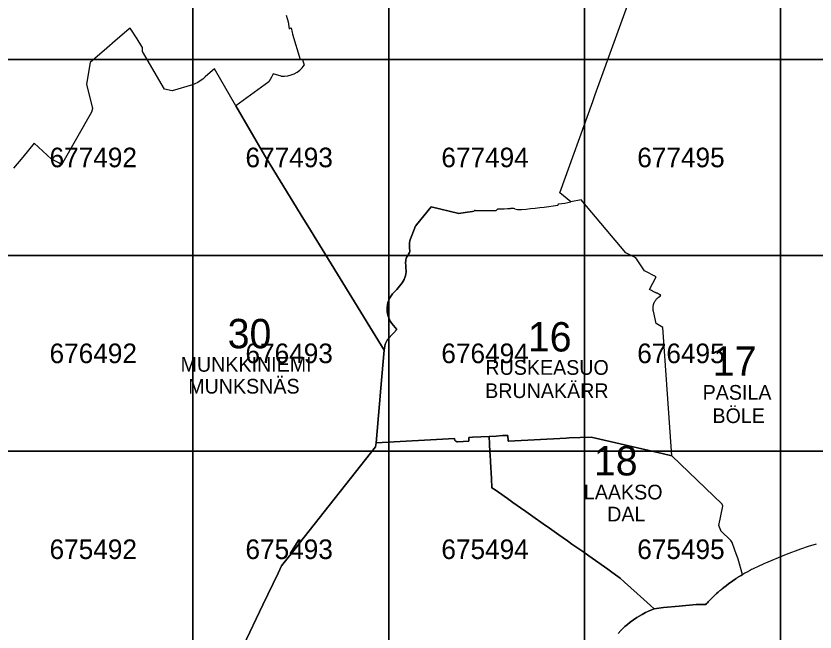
# Model space of a CAD drawing. Extents: x 25485000 to 25520000, y 6656775 to 6690000.
# Drawn here: x 25492097 to 25496176, y 6675077 to 6678222 of the extents above; entities that cross this region are included whole.
import ezdxf

# ---------------------------------------------------------------- set-up
doc = ezdxf.new("R2010")
doc.units = 0
doc.layers.add('Level 63', color=7, linetype='Continuous')

msp = doc.modelspace()

# ---------------------------------------------------------------- linework, layer by layer
at = {"layer": 'Level 63'}
for p, q in [((25494867.2, 6677262.5), (25494862.9, 6677256.6)), ((25494862.9, 6677256.6), (25494867.2, 6677262.5)), ((25494556.1, 6677237.5), (25494547.8, 6677228.8)), ((25494547.8, 6677228.8), (25494556.1, 6677237.5))]:
    msp.add_line(p, q, dxfattribs=at)
for points in [[(25492000, 6678000), (25493000, 6678000), (25493000, 6679000), (25492000, 6679000)], [(25493000, 6678000), (25494000, 6678000), (25494000, 6679000), (25493000, 6679000)], [(25494000, 6678000), (25495000, 6678000), (25495000, 6679000), (25494000, 6679000)], [(25495000, 6678000), (25496000, 6678000), (25496000, 6679000), (25495000, 6679000)], [(25496000, 6678000), (25497000, 6678000), (25497000, 6679000), (25496000, 6679000)], [(25492000, 6677000), (25493000, 6677000), (25493000, 6678000), (25492000, 6678000)], [(25493000, 6677000), (25494000, 6677000), (25494000, 6678000), (25493000, 6678000)], [(25494000, 6677000), (25495000, 6677000), (25495000, 6678000), (25494000, 6678000)], [(25495000, 6677000), (25496000, 6677000), (25496000, 6678000), (25495000, 6678000)], [(25496000, 6677000), (25497000, 6677000), (25497000, 6678000), (25496000, 6678000)], [(25492000, 6676000), (25493000, 6676000), (25493000, 6677000), (25492000, 6677000)], [(25493000, 6676000), (25494000, 6676000), (25494000, 6677000), (25493000, 6677000)], [(25494000, 6676000), (25495000, 6676000), (25495000, 6677000), (25494000, 6677000)], [(25495000, 6676000), (25496000, 6676000), (25496000, 6677000), (25495000, 6677000)], [(25496000, 6676000), (25497000, 6676000), (25497000, 6677000), (25496000, 6677000)], [(25492000, 6675000), (25493000, 6675000), (25493000, 6676000), (25492000, 6676000)], [(25493000, 6675000), (25494000, 6675000), (25494000, 6676000), (25493000, 6676000)], [(25494000, 6675000), (25495000, 6675000), (25495000, 6676000), (25494000, 6676000)], [(25495000, 6675000), (25496000, 6675000), (25496000, 6676000), (25495000, 6676000)], [(25496000, 6675000), (25497000, 6675000), (25497000, 6676000), (25496000, 6676000)]]:
    msp.add_lwpolyline(points, close=True, dxfattribs=at)
for points in [[(25494930, 6677273.2), (25494873.2, 6677319.8), (25495041.5, 6677785.5), (25495054.3, 6677820.9), (25495268.2, 6678413.1), (25495215.7, 6678541.1), (25495718.8, 6678613.4), (25495730.8, 6678521.1), (25495717.9, 6678464.7), (25495669.7, 6678351.7), (25495635.3, 6678309), (25495643.8, 6678288.7), (25495688, 6678307.4), (25496365.4, 6678399)], [(25494930, 6677273.2), (25494873.2, 6677319.8), (25495041.5, 6677785.5), (25495054.3, 6677820.9), (25495268.2, 6678413.1)], [(25493476.1, 6678226.4), (25493486.4, 6678192), (25493490.8, 6678156.8), (25493502.3, 6678161.7), (25493506.8, 6678137.1), (25493508.3, 6678131.3), (25493509.4, 6678129.8), (25493548.5, 6678000.4), (25493559.1, 6677999.8), (25493569, 6677970.9)], [(25493476.1, 6678226.4), (25493486.4, 6678192), (25493490.8, 6678156.8), (25493502.3, 6678161.7), (25493506.8, 6678137.1), (25493508.3, 6678131.3), (25493509.4, 6678129.8), (25493548.5, 6678000.4), (25493559.1, 6677999.8), (25493569, 6677970.9)], [(25493451.2, 6677915), (25493409.8, 6677926.4), (25493401.5, 6677910.3), (25493388.4, 6677886.6), (25493219.5, 6677763.4), (25493110.5, 6677952.1), (25493088.7, 6677933.2), (25493062.7, 6677910.8), (25493050.5, 6677900.3), (25493050.5, 6677900.2), (25493038.1, 6677890.6), (25493024.7, 6677882.3), (25493010.6, 6677875.5), (25492997.5, 6677870.4), (25492893.9, 6677840.4), (25492855.7, 6677847.8), (25492742.1, 6678040.9), (25492743.5, 6678060.9), (25492740.2, 6678065.9), (25492715.1, 6678104.8), (25492679.4, 6678160.1), (25492672.9, 6678154.5), (25492604.1, 6678095.1), (25492560.2, 6678057.3), (25492476.6, 6677985.1), (25492457.2, 6677874.2), (25492487.4, 6677749.3), (25492482.8, 6677731.1), (25492329.6, 6677462.8), (25492315.7, 6677472.7), (25492278.6, 6677491.7), (25492190.4, 6677572.6), (25492132.8, 6677501.1), (25492083.6, 6677444.5)], [(25493156.6, 6674793.6), (25493358, 6675216.5), (25493434.7, 6675377.4), (25493452.6, 6675415.1), (25493535.6, 6675519.9), (25493542.7, 6675528.8), (25493933, 6676022), (25493934.9, 6676043.6), (25493964.7, 6676381), (25493976.6, 6676516), (25493586.6, 6677150.8), (25493566.1, 6677184.1), (25493375.5, 6677494.5), (25493365.2, 6677511.2), (25493219.5, 6677763.4), (25493110.5, 6677952.1), (25493088.7, 6677933.2), (25493062.7, 6677910.8), (25493050.5, 6677900.3), (25493050.5, 6677900.2), (25493038.1, 6677890.6), (25493024.7, 6677882.3), (25493010.6, 6677875.5), (25492997.5, 6677870.4), (25492893.9, 6677840.4), (25492855.7, 6677847.8), (25492742.1, 6678040.9), (25492743.5, 6678060.9), (25492740.2, 6678065.9), (25492715.1, 6678104.8), (25492679.4, 6678160.1), (25492672.9, 6678154.5), (25492604.1, 6678095.1), (25492560.2, 6678057.3), (25492476.6, 6677985.1), (25492457.2, 6677874.2), (25492487.4, 6677749.3), (25492482.8, 6677731.1), (25492329.6, 6677462.8), (25492315.7, 6677472.7), (25492278.6, 6677491.7), (25492190.4, 6677572.6), (25492132.8, 6677501.1), (25492083.6, 6677444.5)], [(25493451.2, 6677915), (25493409.8, 6677926.4), (25493401.5, 6677910.3), (25493388.4, 6677886.6), (25493219.5, 6677763.4), (25493365.2, 6677511.2), (25493375.5, 6677494.5), (25493566.1, 6677184.1), (25493586.6, 6677150.8), (25493976.6, 6676516), (25493982.3, 6676547.4), (25493994.3, 6676570.4), (25494023.9, 6676603.1), (25494040.6, 6676621.7), (25494016.3, 6676653.1), (25494009.3, 6676663.2), (25494004.1, 6676672.5), (25494000.4, 6676680.6), (25493997.8, 6676687.7), (25493995.4, 6676695.7), (25493993.8, 6676703.2), (25493992.5, 6676709.8), (25493991.4, 6676722.3), (25493991.6, 6676734.8), (25493993.2, 6676747.3), (25493996, 6676759.5), (25494000.1, 6676771.4), (25494005.4, 6676782.8), (25494011.9, 6676793.6), (25494019.4, 6676803.6), (25494028, 6676812.8), (25494040.8, 6676825.1), (25494068.3, 6676860.4), (25494074, 6676868.6), (25494078.8, 6676877.3), (25494082.7, 6676886.5), (25494085.6, 6676896), (25494087.4, 6676905.7), (25494088.3, 6676915.7), (25494088.1, 6676925.6), (25494087.7, 6676929.6), (25494086.9, 6676946.7), (25494086.2, 6676963.2), (25494086.1, 6676965.2), (25494086.4, 6676971.4), (25494087.3, 6676977.6), (25494088.9, 6676983.7), (25494091, 6676989.6), (25494093.8, 6676995.2), (25494105.1, 6677015.3), (25494106, 6677017.2), (25494106.8, 6677019.2), (25494107.3, 6677021.2), (25494107.6, 6677023.3), (25494107.7, 6677025.4), (25494107.5, 6677027.5), (25494107.3, 6677029.2), (25494106.6, 6677032.6), (25494105.4, 6677043), (25494105.3, 6677053.4), (25494106.3, 6677063.8), (25494108.3, 6677074.1), (25494111.5, 6677084.1), (25494132.7, 6677141.2), (25494133.1, 6677142.2), (25494135.3, 6677147), (25494137.9, 6677151.5), (25494141, 6677155.7), (25494217, 6677247.5), (25494358.3, 6677214.1), (25494390.3, 6677219.8), (25494427.9, 6677224.3), (25494435.8, 6677225.3)], [(25493934.9, 6676043.6), (25494335.5, 6676066.1), (25494335.7, 6676063.1), (25494335.8, 6676061.6), (25494336.2, 6676060), (25494336.6, 6676058.5), (25494337.3, 6676057.1), (25494338.1, 6676055.7), (25494339, 6676054.5), (25494340.1, 6676053.3), (25494341.2, 6676052.3), (25494342.5, 6676051.3), (25494343.9, 6676050.6), (25494345.3, 6676049.9), (25494346.8, 6676049.5), (25494348.3, 6676049.1), (25494349.9, 6676049), (25494351.5, 6676049), (25494409.4, 6676052.2), (25494408.4, 6676070.2), (25494427.3, 6676071.3), (25494512.2, 6676076), (25494548.1, 6676078), (25494581.2, 6676079.9), (25494608.2, 6676081.4), (25494609.9, 6676051.6), (25494610.1, 6676051.7), (25494610.9, 6676051.9), (25494611.7, 6676052), (25494905.8, 6676067.2), (25494921.1, 6676068.2), (25495032.7, 6676071.4), (25495395.1, 6675987.9), (25495445.1, 6675976.4), (25495399.3, 6676631.9), (25495365.7, 6676652.8), (25495350.9, 6676716), (25495350.5, 6676717.6), (25495350.3, 6676718.9), (25495350.1, 6676719.9), (25495349.7, 6676722.2), (25495349.7, 6676722.7), (25495349.6, 6676723.3), (25495349.5, 6676724.4), (25495349.4, 6676726), (25495349.3, 6676727.4), (25495349.2, 6676729.5), (25495349.2, 6676730), (25495349.2, 6676730.6), (25495349.2, 6676731.4), (25495349.2, 6676732), (25495349.2, 6676734), (25495349.4, 6676736.3), (25495349.6, 6676738.2), (25495349.9, 6676740.3), (25495350.3, 6676743), (25495350.8, 6676745.3), (25495351, 6676746.2), (25495351.3, 6676747.3), (25495351.5, 6676747.9), (25495352, 6676749.6), (25495352.2, 6676750.5), (25495353.3, 6676753.6), (25495353.7, 6676754.8), (25495353.8, 6676755.1), (25495354, 6676755.5), (25495354.2, 6676755.9), (25495355, 6676757.8), (25495355.7, 6676759.3), (25495356.7, 6676761.6), (25495358.5, 6676764.9), (25495360.2, 6676767.6), (25495362.7, 6676771.5), (25495365, 6676774.4), (25495367.6, 6676777.6), (25495369.4, 6676779.5), (25495371.1, 6676781.2), (25495373.2, 6676783.2), (25495374.6, 6676784.5), (25495376.7, 6676786.2), (25495378, 6676787.3), (25495378.6, 6676787.7), (25495379.2, 6676788.2), (25495379.7, 6676788.5), (25495380, 6676788.7), (25495380.8, 6676789.3), (25495385, 6676792.2), (25495388.2, 6676797.3), (25495387.4, 6676797.8), (25495386.4, 6676798.4), (25495385.4, 6676799), (25495384.6, 6676799.5), (25495382.5, 6676800.6), (25495380.5, 6676801.7), (25495378.7, 6676802.5), (25495377, 6676803.3), (25495374.9, 6676804.2), (25495369.7, 6676806.4), (25495367.2, 6676807.5), (25495364.3, 6676808.8), (25495362.8, 6676809.4), (25495360.9, 6676810.3), (25495359.5, 6676810.9), (25495356.1, 6676812.5), (25495353, 6676814.1), (25495346.8, 6676817.1), (25495340.7, 6676820.3), (25495331.5, 6676825.3), (25495365.4, 6676890.2), (25495306.1, 6676921.2), (25495260.6, 6676987.2), (25495210.5, 6677013.3), (25494982.7, 6677284.2), (25494930, 6677273.2)], [(25495745.6, 6675545.2), (25495695.7, 6675594.7), (25495694.5, 6675595.9), (25495685.8, 6675621.4), (25495705, 6675719.4), (25495701.4, 6675730.1), (25495445.1, 6675976.4), (25495399.3, 6676631.9), (25495365.7, 6676652.8), (25495350.9, 6676716), (25495350.5, 6676717.6), (25495350.3, 6676718.9), (25495350.1, 6676719.9), (25495349.7, 6676722.2), (25495349.7, 6676722.7), (25495349.6, 6676723.3), (25495349.5, 6676724.4), (25495349.4, 6676726), (25495349.3, 6676727.4), (25495349.2, 6676729.5), (25495349.2, 6676730), (25495349.2, 6676730.6), (25495349.2, 6676731.4), (25495349.2, 6676732), (25495349.2, 6676734), (25495349.4, 6676736.3), (25495349.6, 6676738.2), (25495349.9, 6676740.3), (25495350.3, 6676743), (25495350.8, 6676745.3), (25495351, 6676746.2), (25495351.3, 6676747.3), (25495351.5, 6676747.9), (25495352, 6676749.6), (25495352.2, 6676750.5), (25495353.3, 6676753.6), (25495353.7, 6676754.8), (25495353.8, 6676755.1), (25495354, 6676755.5), (25495354.2, 6676755.9), (25495355, 6676757.8), (25495355.7, 6676759.3), (25495356.7, 6676761.6), (25495358.5, 6676764.9), (25495360.2, 6676767.6), (25495362.7, 6676771.5), (25495365, 6676774.4), (25495367.6, 6676777.6), (25495369.4, 6676779.5), (25495371.1, 6676781.2), (25495373.2, 6676783.2), (25495374.6, 6676784.5), (25495376.7, 6676786.2), (25495378, 6676787.3), (25495378.6, 6676787.7), (25495379.2, 6676788.2), (25495379.7, 6676788.5), (25495380, 6676788.7), (25495380.8, 6676789.3), (25495385, 6676792.2), (25495388.2, 6676797.3), (25495387.4, 6676797.8), (25495386.4, 6676798.4), (25495385.4, 6676799), (25495384.6, 6676799.5), (25495382.5, 6676800.6), (25495380.5, 6676801.7), (25495378.7, 6676802.5), (25495377, 6676803.3), (25495374.9, 6676804.2), (25495369.7, 6676806.4), (25495367.2, 6676807.5), (25495364.3, 6676808.8), (25495362.8, 6676809.4), (25495360.9, 6676810.3), (25495359.5, 6676810.9), (25495356.1, 6676812.5), (25495353, 6676814.1), (25495346.8, 6676817.1), (25495340.7, 6676820.3), (25495331.5, 6676825.3), (25495365.4, 6676890.2), (25495306.1, 6676921.2), (25495260.6, 6676987.2), (25495210.5, 6677013.3), (25494982.7, 6677284.2), (25494930, 6677273.2)], [(25494435.8, 6677225.3), (25494427.9, 6677224.3), (25494390.3, 6677219.8), (25494358.3, 6677214.1), (25494217, 6677247.5), (25494141, 6677155.7), (25494137.9, 6677151.5), (25494135.3, 6677147), (25494133.1, 6677142.2), (25494132.7, 6677141.2), (25494111.5, 6677084.1), (25494108.3, 6677074.1), (25494106.3, 6677063.8), (25494105.3, 6677053.4), (25494105.4, 6677043), (25494106.6, 6677032.6), (25494107.3, 6677029.2), (25494107.5, 6677027.5), (25494107.7, 6677025.4), (25494107.6, 6677023.3), (25494107.3, 6677021.2), (25494106.8, 6677019.2), (25494106, 6677017.2), (25494105.1, 6677015.3), (25494093.8, 6676995.2), (25494091, 6676989.6), (25494088.9, 6676983.7), (25494087.3, 6676977.6), (25494086.4, 6676971.4), (25494086.1, 6676965.2), (25494086.2, 6676963.2), (25494086.9, 6676946.7), (25494087.7, 6676929.6), (25494088.1, 6676925.6), (25494088.3, 6676915.7), (25494087.4, 6676905.7), (25494085.6, 6676896), (25494082.7, 6676886.5), (25494078.8, 6676877.3), (25494074, 6676868.6), (25494068.3, 6676860.4), (25494040.8, 6676825.1), (25494028, 6676812.8), (25494019.4, 6676803.6), (25494011.9, 6676793.6), (25494005.4, 6676782.8), (25494000.1, 6676771.4), (25493996, 6676759.5), (25493993.2, 6676747.3), (25493991.6, 6676734.8), (25493991.4, 6676722.3), (25493992.5, 6676709.8), (25493993.8, 6676703.2), (25493995.4, 6676695.7), (25493997.8, 6676687.7), (25494000.4, 6676680.6), (25494004.1, 6676672.5), (25494009.3, 6676663.2), (25494016.3, 6676653.1), (25494040.6, 6676621.7), (25494023.9, 6676603.1), (25493994.3, 6676570.4), (25493982.3, 6676547.4), (25493976.6, 6676516), (25493964.7, 6676381), (25493934.9, 6676043.6)], [(25495745.6, 6675545.2), (25495695.7, 6675594.7), (25495694.5, 6675595.9), (25495685.8, 6675621.4), (25495705, 6675719.4), (25495701.4, 6675730.1), (25495445.1, 6675976.4), (25495395.1, 6675987.9), (25495032.7, 6676071.4), (25494921.1, 6676068.2), (25494905.8, 6676067.2), (25494611.7, 6676052), (25494610.9, 6676051.9), (25494610.1, 6676051.7), (25494609.9, 6676051.6), (25494608.2, 6676081.4), (25494581.2, 6676079.9), (25494548.1, 6676078), (25494512.2, 6676076)], [(25495170.4, 6675070), (25495185, 6675084.7), (25495190.2, 6675089.7), (25495205.9, 6675104.9), (25495218.7, 6675116.2), (25495232.3, 6675127.1), (25495266.4, 6675151.3), (25495293.2, 6675167.2), (25495311.4, 6675176.6), (25495326.1, 6675183.5), (25495354.2, 6675196), (25495335.3, 6675213), (25495268, 6675273.4), (25495235.3, 6675302.9), (25495202.6, 6675332.3), (25495181, 6675351.7), (25495169.5, 6675360.1), (25495138.8, 6675382.7), (25495118.7, 6675397.6), (25495022.1, 6675465.6), (25494995.3, 6675484.4), (25494974.6, 6675499), (25494955, 6675512.8), (25494935.4, 6675526.6), (25494912.5, 6675542.7), (25494868, 6675574), (25494844.3, 6675590.7), (25494820.6, 6675607.4), (25494788.4, 6675630.1), (25494776.2, 6675638.7), (25494746.7, 6675659.4), (25494722.9, 6675676.1), (25494699.2, 6675692.8), (25494672.2, 6675711.9), (25494655.8, 6675723.4), (25494633.3, 6675739.2), (25494605.5, 6675758.8), (25494560.1, 6675790.7), (25494542.6, 6675803.1), (25494526.9, 6675814.1), (25494524.2, 6675861.8), (25494519.5, 6675946.7), (25494517.4, 6675983), (25494516.7, 6675996), (25494514.4, 6676037.4), (25494512.2, 6676076), (25494427.3, 6676071.3), (25494408.4, 6676070.2), (25494409.4, 6676052.2), (25494351.5, 6676049), (25494349.9, 6676049), (25494348.3, 6676049.1), (25494346.8, 6676049.5), (25494345.3, 6676049.9), (25494343.9, 6676050.6), (25494342.5, 6676051.3), (25494341.2, 6676052.3), (25494340.1, 6676053.3), (25494339, 6676054.5), (25494338.1, 6676055.7), (25494337.3, 6676057.1), (25494336.6, 6676058.5), (25494336.2, 6676060), (25494335.8, 6676061.6), (25494335.7, 6676063.1), (25494335.5, 6676066.1), (25493934.9, 6676043.6), (25493933, 6676022), (25493542.7, 6675528.8), (25493535.6, 6675519.9), (25493452.6, 6675415.1), (25493434.7, 6675377.4), (25493358, 6675216.5), (25493156.6, 6674793.6)], [(25494512.2, 6676076), (25494514.4, 6676037.4), (25494516.7, 6675996), (25494517.4, 6675983), (25494519.5, 6675946.7), (25494524.2, 6675861.8), (25494526.9, 6675814.1), (25494542.6, 6675803.1), (25494560.1, 6675790.7), (25494605.5, 6675758.8), (25494633.3, 6675739.2), (25494655.8, 6675723.4), (25494672.2, 6675711.9), (25494699.2, 6675692.8), (25494722.9, 6675676.1), (25494746.7, 6675659.4), (25494776.2, 6675638.7), (25494788.4, 6675630.1), (25494820.6, 6675607.4), (25494844.3, 6675590.7), (25494868, 6675574), (25494912.5, 6675542.7), (25494935.4, 6675526.6), (25494955, 6675512.8), (25494974.6, 6675499), (25494995.3, 6675484.4), (25495022.1, 6675465.6), (25495118.7, 6675397.6), (25495138.8, 6675382.7), (25495169.5, 6675360.1), (25495181, 6675351.7), (25495202.6, 6675332.3), (25495235.3, 6675302.9), (25495268, 6675273.4), (25495335.3, 6675213), (25495354.2, 6675196), (25495401.9, 6675203), (25495483, 6675209.8), (25495569.7, 6675217.3), (25495618.7, 6675218.7), (25495622.8, 6675223.1), (25495624.1, 6675224.6), (25495625.5, 6675226.1), (25495625.8, 6675226.4), (25495626.3, 6675227), (25495630.3, 6675231.1), (25495633.5, 6675234.5), (25495638.6, 6675239.8), (25495643.6, 6675244.9), (25495658.2, 6675259.2), (25495663.1, 6675263.8), (25495666.4, 6675266.9), (25495670.5, 6675270.7), (25495672.3, 6675272.3), (25495673.9, 6675273.7), (25495681.5, 6675280.5), (25495688.9, 6675287), (25495692.3, 6675289.9), (25495695.2, 6675292.3), (25495696.6, 6675293.5), (25495702.2, 6675298.2), (25495710.4, 6675304.8), (25495722, 6675313.9), (25495735.9, 6675324.4), (25495743.7, 6675330.1), (25495755.8, 6675338.7), (25495768.9, 6675347.5), (25495773.7, 6675350.6), (25495775.9, 6675352.1), (25495778.5, 6675353.8), (25495781.1, 6675355.4), (25495783.7, 6675357.1), (25495786.1, 6675358.5), (25495792.9, 6675362.8), (25495799.2, 6675366.6), (25495806.4, 6675370.9), (25495784.2, 6675449), (25495767.1, 6675495.2), (25495752.6, 6675534.3)], [(25496181, 6675525.5), (25496141, 6675513.5), (25496102, 6675501.1), (25496029, 6675473.2), (25495915.4, 6675425.8), (25495881.9, 6675409.8), (25495866.6, 6675402.8), (25495857, 6675398.1), (25495852.2, 6675395.7), (25495847.4, 6675393.3), (25495840.6, 6675389.8), (25495837.5, 6675388.1), (25495834.5, 6675386.6), (25495832.3, 6675385.4), (25495832, 6675385.2), (25495831.5, 6675384.9), (25495830.9, 6675384.7), (25495828.9, 6675383.6), (25495825.1, 6675381.5), (25495817.8, 6675377.4), (25495807.5, 6675371.5), (25495806.4, 6675370.9), (25495799.2, 6675366.6), (25495792.9, 6675362.8), (25495786.1, 6675358.5), (25495783.7, 6675357.1), (25495781.1, 6675355.4), (25495778.5, 6675353.8), (25495775.9, 6675352.1), (25495773.7, 6675350.6), (25495768.9, 6675347.5), (25495755.8, 6675338.7), (25495743.7, 6675330.1), (25495735.9, 6675324.4), (25495722, 6675313.9), (25495710.4, 6675304.8), (25495702.2, 6675298.2), (25495696.6, 6675293.5), (25495695.2, 6675292.3), (25495692.3, 6675289.9), (25495688.9, 6675287), (25495681.5, 6675280.5), (25495673.9, 6675273.7), (25495672.3, 6675272.3), (25495670.5, 6675270.7), (25495666.4, 6675266.9), (25495663.1, 6675263.8), (25495658.2, 6675259.2), (25495643.6, 6675244.9), (25495638.6, 6675239.8), (25495633.5, 6675234.5), (25495630.3, 6675231.1), (25495626.3, 6675227), (25495625.8, 6675226.4), (25495625.5, 6675226.1), (25495624.1, 6675224.6), (25495622.8, 6675223.1), (25495618.7, 6675218.7), (25495569.7, 6675217.3), (25495483, 6675209.8), (25495401.9, 6675203), (25495354.2, 6675196), (25495326.1, 6675183.5), (25495311.4, 6675176.6), (25495293.2, 6675167.2), (25495266.4, 6675151.3), (25495232.3, 6675127.1), (25495218.7, 6675116.2), (25495205.9, 6675104.9), (25495190.2, 6675089.7), (25495185, 6675084.7), (25495170.4, 6675070)], [(25496181, 6675525.5), (25496141, 6675513.5), (25496102, 6675501.1), (25496029, 6675473.2), (25495915.4, 6675425.8), (25495881.9, 6675409.8), (25495866.6, 6675402.8), (25495857, 6675398.1), (25495852.2, 6675395.7), (25495847.4, 6675393.3), (25495840.6, 6675389.8), (25495837.5, 6675388.1), (25495834.5, 6675386.6), (25495832.3, 6675385.4), (25495832, 6675385.2), (25495831.5, 6675384.9), (25495830.9, 6675384.7), (25495828.9, 6675383.6), (25495825.1, 6675381.5), (25495817.8, 6675377.4), (25495807.5, 6675371.5), (25495806.4, 6675370.9), (25495784.2, 6675449), (25495767.1, 6675495.2), (25495752.6, 6675534.3)]]:
    msp.add_lwpolyline(points, dxfattribs=at)
for centre, radius, start, end in [((25493459.4, 6678049.7), 135, 266.5065, 324.2807), ((25493459.4, 6678049.7), 135, 266.5065, 324.2807), ((25494757.5, 6678097.3), 842, 277.4863, 281.8255), ((25494757.5, 6678097.3), 842, 277.4862, 281.8256), ((25494440.3, 6677225.1), 4.5, 88.1936, 177.823), ((25494440.3, 6677225.1), 4.5, 88.1936, 177.823), ((25494510.6, 6679468.4), 2239.9, 268.2061, 270.953), ((25494510.6, 6679468.4), 2239.9, 268.2061, 270.953), ((25494510.5, 6679452), 2215, 271.1814, 272.88), ((25494510.5, 6679452), 2215, 271.1814, 272.88), ((25494625.2, 6677170.9), 69, 74.133, 92.8797), ((25494625.2, 6677170.9), 69, 74.133, 92.8797), ((25494666.2, 6677315.2), 81, 254.1329, 274.1687), ((25494666.2, 6677315.2), 81, 254.1329, 274.1687), ((25494465.1, 6680061.9), 2835.1, 274.1876, 274.303), ((25494465.1, 6680061.9), 2835.1, 274.1876, 274.303), ((25494503.2, 6679514.1), 2285.9, 274.3808, 279.0542), ((25494503.2, 6679514.1), 2285.9, 274.3808, 279.0542), ((25495724.5, 6675523.9), 30, 20.3021, 45.2636), ((25495724.5, 6675523.9), 30, 20.3021, 45.2636)]:
    msp.add_arc(centre, radius, start, end, dxfattribs=at)

# ---------------------------------------------------------------- texts
for s, height, p in [('677492', 100, (25492268.5, 6677450)), ('677493', 100, (25493268.5, 6677450)), ('677494', 100, (25494268.5, 6677450)), ('677495', 100, (25495268.5, 6677450)), ('30', 150, (25493177.7, 6676525.8)), ('16', 150, (25494710, 6676509.5)), ('676492', 100, (25492268.5, 6676450)), ('676493', 100, (25493268.5, 6676450)), ('676494', 100, (25494268.5, 6676450)), ('676495', 100, (25495268.5, 6676450)), ('17', 150, (25495654.1, 6676385.7)), ('MUNKKINIEMI', 75, (25492937.3, 6676406.1)), ('RUSKEASUO', 75, (25494493.4, 6676390.4)), ('MUNKSNÄS', 75, (25492976.5, 6676294.7)), ('BRUNAKÄRR', 75, (25494492.3, 6676271.8)), ('PASILA', 75, (25495602.3, 6676263.3)), ('BÖLE', 75, (25495652.3, 6676144.1)), ('18', 150, (25495047.1, 6675876.7)), ('LAAKSO', 75, (25494996.1, 6675754.3)), ('DAL', 75, (25495115.2, 6675641.9)), ('675492', 100, (25492268.5, 6675450)), ('675493', 100, (25493268.5, 6675450)), ('675494', 100, (25494268.5, 6675450)), ('675495', 100, (25495268.5, 6675450))]:
    msp.add_text(s, height=height, dxfattribs=at).set_placement(p)

doc.saveas('drawing.dxf')
